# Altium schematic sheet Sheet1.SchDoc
size A4
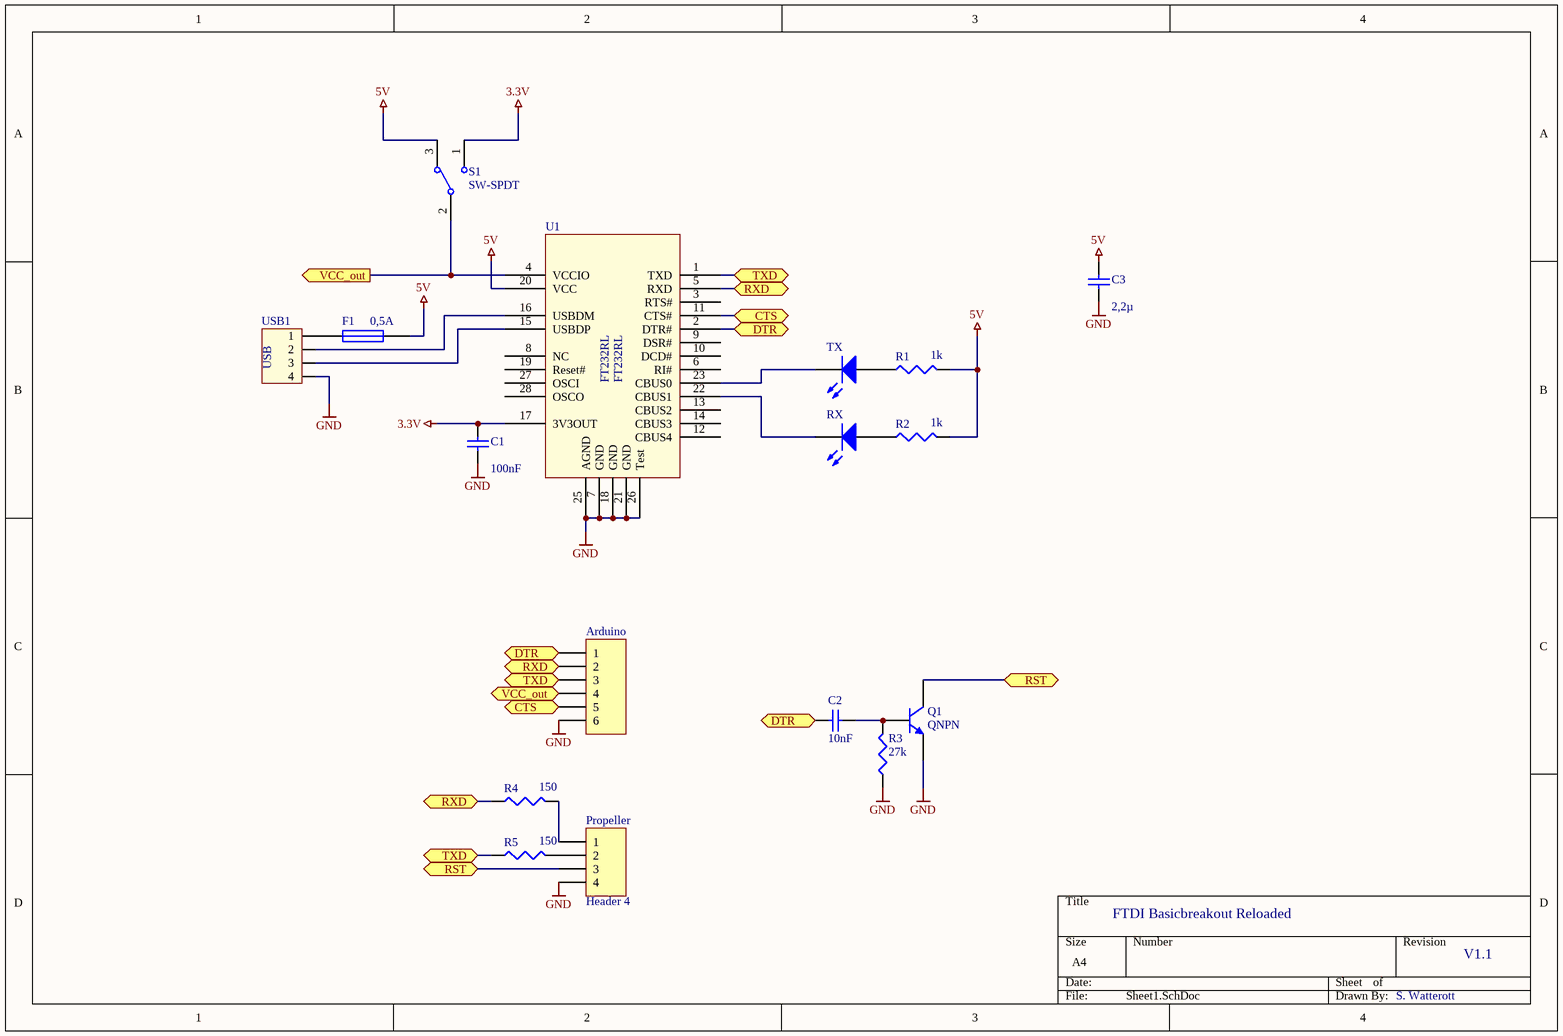
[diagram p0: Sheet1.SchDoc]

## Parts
Arduino  Header 6H  [HDR1X6]  (value not drawn)
C1  value 100nF  [0603]  (hidden comment: C0603)
C2  10nF  [0603]
C3  2,2µ  [0603]
F1  0,5A  [2220]
Propeller  Header 4  [HDR1X4]
Q1  QNPN  [SOT-23B]
R1  1k  [RESC1608L]
R2  1k  [RESC1608L]
R3  27k  [RESC1608L]
R4  150  [RESC1608L]
R5  150  [RESC1608L]
RX  LED2  [RESC1608L]  (value not drawn)
S1  SW-SPDT  [SMD Switch]
TX  LED2  [RESC1608L]  (value not drawn)
U1  FT232RL  [DB028]
USB1  USB_Con  [Molex 548190572]  (value not drawn)

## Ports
CTS, DTR, RST, RXD, TXD, VCC_out (in), VCC_out (out)

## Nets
3.3V: C1.2 S1.1 U1.17(3V3OUT)
5V: C3.2 F1.2 R1.2 R2.2 S1.3 U1.20(VCC)
GND: Arduino.6 C1.1 C3.1 Propeller.4 Q1.3(E) R3.1 U1.7(GND) U1.18(GND) U1.21(GND) U1.25(AGND) U1.26(Test) USB1.4
CTS: Arduino.5 U1.11(CTS#) ; port CTS
DTR: Arduino.1 C2.2 U1.2(DTR#) ; port DTR
RST: Propeller.3 Q1.1(C) ; port RST
RXD: Arduino.2 R4.1 U1.5(RXD) ; port RXD
TXD: Arduino.3 R5.1 U1.1(TXD) ; port TXD
VCC_out: Arduino.4 S1.2 U1.4(VCCIO) ; port VCC_out
NetC2_1: C2.1 Q1.2(B) R3.2
NetF1_1: F1.1 USB1.1
NetPropeller_1: Propeller.1 R4.2
NetPropeller_2: Propeller.2 R5.2
NetR1_1: R1.1 TX.1(A)
NetR2_1: R2.1 RX.1(A)
NetRX_2: RX.2(K) U1.22(CBUS1)
NetTX_2: TX.2(K) U1.23(CBUS0)
NetU1_15: U1.15(USBDP) USB1.3
NetU1_16: U1.16(USBDM) USB1.2

Not connected (* = marked no-connect by the designer): U1 3(RTS#) 6(RI#) 8(NC) 9(DSR#) 10(DCD#) 12(CBUS4) 13(CBUS2) 14(CBUS3) 19(Reset#) 27(OSCI) 28(OSCO)

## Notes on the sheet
- FTDI Basicbreakout Reloaded
- V1.1
- S. Watterott

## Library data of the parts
Arduino = Header 6H: Header, 6-Pin, Right Angle
C1-C3 = C0603: Ceramic Chip Capacitor - Standard; Note: Footprint corresponds to dimensions for bulk cassette packaging. This case size has tightened tolerances.
F1 = Fuse 1: Fuse
Propeller = Header 4: Header, 4-Pin
Q1 = QNPN: NPN Bipolar Transistor; pin to pad: 1>3 2>1 3>2
R1-R5 = Res3: Resistor
RX TX = LED2: Typical RED, GREEN, YELLOW, AMBER GaAs LED
S1 = SW-SPDT: SPDT Subminiature Toggle Switch, Right Angle Mounting, Vertical Actuation
U1 = FT232RQ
